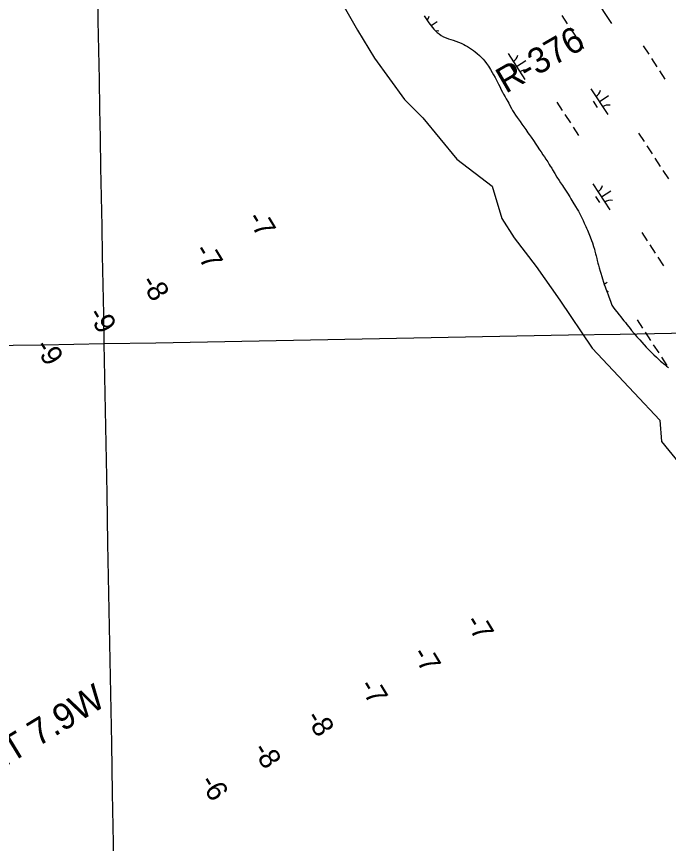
# Model space of a CAD drawing. Extents: x 3953924 to 3974542, y 193747 to 216192.
# Drawn here: x 3962352 to 3963404, y 205562 to 206897 of the extents above; entities that cross this region are included whole.
import ezdxf

# ---------------------------------------------------------------- set-up
doc = ezdxf.new("R2010")
doc.units = 0
for name, color, linetype in [('V-GRID-MAJR', 7, 'Continuous'), ('V-RIVR-EDGE', 7, 'Continuous'), ('V-RIVR-RANG', 7, 'Continuous'), ('V-RIVR-RANG-IDEN', 7, 'Continuous'), ('V-RRAP-SILL-IDEN', 7, 'Continuous'), ('V-WETL-SWMP', 7, 'Continuous')]:
    doc.layers.add(name, color=color, linetype=linetype)

msp = doc.modelspace()

# ---------------------------------------------------------------- linework, layer by layer
at = {"layer": 'V-GRID-MAJR'}
for points in [[(3962589.8, 201207.1), (3962493.7, 206368.6), (3962380.9, 212428.6), (3962369.3, 213053.2)], [(3959356.8, 206310.4), (3962493.7, 206368.6), (3967818.6, 206468.2), (3970066, 206510.4)]]:
    msp.add_spline(points, degree=3, dxfattribs=at)
at = {"layer": 'V-RIVR-EDGE'}
msp.add_lwpolyline([(3962880.7, 206912.3), (3962902.1, 206874.3), (3962929.4, 206829.2), (3962978.1, 206762.8), (3963007.8, 206733.1), (3963062.4, 206666.6), (3963119.4, 206622.7), (3963134.8, 206570.4), (3963155, 206539.6), (3963190.6, 206493.3), (3963228.6, 206438.6), (3963280.8, 206361.5), (3963348.5, 206289.1), (3963390.1, 206245.1), (3963392.4, 206210.7), (3963466, 206120.5), (3963492.2, 206108.6), (3963506.4, 206087.2), (3963530.1, 206054), (3963552.7, 206032.6), (3963582.4, 206007.7), (3963606.1, 205985.1), (3963619, 205957.3)], dxfattribs=at)
at = {"layer": 'V-WETL-SWMP'}
for p, q in [((3963284.5, 206927.4), (3963311.8, 206885.5)), ((3963231.7, 206898.4), (3963240.5, 206885)), ((3963009.8, 206897.7), (3963012, 206894.3)), ((3963012, 206894.3), (3963014.1, 206891.1)), ((3963014.1, 206891.1), (3963017.4, 206886.6)), ((3963017.4, 206886.6), (3963019.4, 206883.8)), ((3963020.8, 206882), (3963030.9, 206888.5)), ((3963019.4, 206883.8), (3963023.2, 206879)), ((3963023.2, 206879), (3963025.3, 206876.4)), ((3963025.3, 206876.4), (3963028.5, 206873.1)), ((3963028.5, 206873.1), (3963030.8, 206870.9)), ((3963244.8, 206878.3), (3963253.6, 206864.9)), ((3963030.8, 206870.9), (3963033.8, 206868.5)), ((3963033.8, 206868.5), (3963037.2, 206866.1)), ((3963037.2, 206866.1), (3963040.8, 206863.9)), ((3963040.8, 206863.9), (3963045.4, 206862.1)), ((3963045.4, 206862.1), (3963048.9, 206860.8)), ((3963048.9, 206860.8), (3963052.8, 206859.5)), ((3963052.8, 206859.5), (3963056.7, 206858.4)), ((3963056.7, 206858.4), (3963061, 206856.8)), ((3963257.9, 206858.2), (3963266.7, 206844.8)), ((3963061, 206856.8), (3963065.1, 206855.4)), ((3963065.1, 206855.4), (3963069.3, 206853.5)), ((3963069.3, 206853.5), (3963073.7, 206851.4)), ((3963073.7, 206851.4), (3963076.3, 206850)), ((3963076.3, 206850), (3963079.6, 206848.2)), ((3963079.6, 206848.2), (3963082.9, 206846.3)), ((3963082.9, 206846.3), (3963086.1, 206844.1)), ((3963363.1, 206849.1), (3963371.9, 206835.7)), ((3963086.1, 206844.1), (3963089.4, 206842)), ((3963089.4, 206842), (3963092.1, 206839.5)), ((3963092.1, 206839.5), (3963095.3, 206837)), ((3963095.3, 206837), (3963098.8, 206833.8)), ((3963098.8, 206833.8), (3963102.1, 206830.6)), ((3963145.1, 206836.7), (3963172.3, 206794.8)), ((3963102.1, 206830.6), (3963104.8, 206827.6)), ((3963104.8, 206827.6), (3963107.4, 206824.4)), ((3963107.4, 206824.4), (3963110.3, 206820.7)), ((3963110.3, 206820.7), (3963113.4, 206816.5)), ((3963158.7, 206815.7), (3963173.8, 206825.6)), ((3963376.2, 206829), (3963385, 206815.6)), ((3963113.4, 206816.5), (3963116.6, 206811.2)), ((3963116.6, 206811.2), (3963119.5, 206806.4)), ((3963119.5, 206806.4), (3963121.7, 206802.3)), ((3963149, 206816.6), (3963155.5, 206806.5)), ((3963389.3, 206808.9), (3963398.1, 206795.5)), ((3963121.7, 206802.3), (3963124, 206798)), ((3963124, 206798), (3963125.7, 206795.2)), ((3963125.7, 206795.2), (3963127.9, 206790.5)), ((3963127.9, 206790.5), (3963129.6, 206787.3)), ((3963129.6, 206787.3), (3963132.1, 206782.4)), ((3963132.1, 206782.4), (3963133.6, 206779.2)), ((3963133.6, 206779.2), (3963136, 206774.4)), ((3963278.5, 206780.1), (3963305.8, 206738.2)), ((3963136, 206774.4), (3963137.7, 206771.3)), ((3963137.7, 206771.3), (3963140.3, 206766.7)), ((3963140.3, 206766.7), (3963141.9, 206763.8)), ((3963292.1, 206759.1), (3963307.2, 206768.9)), ((3963141.9, 206763.8), (3963144.5, 206759.5)), ((3963144.5, 206759.5), (3963146.2, 206756.8)), ((3963146.2, 206756.8), (3963147.6, 206754.1)), ((3963147.6, 206754.1), (3963150.6, 206748)), ((3963223.7, 206758.4), (3963232.5, 206745)), ((3963282.4, 206759.9), (3963288.9, 206749.9)), ((3963150.6, 206748), (3963152.2, 206744.8)), ((3963152.2, 206744.8), (3963154.1, 206741.8)), ((3963154.1, 206741.8), (3963157.1, 206737.3)), ((3963236.8, 206738.3), (3963245.6, 206724.9)), ((3963157.1, 206737.3), (3963159.6, 206733.7)), ((3963159.6, 206733.7), (3963161.4, 206731.2)), ((3963161.4, 206731.2), (3963164.3, 206727)), ((3963164.3, 206727), (3963167.2, 206723.1)), ((3963167.2, 206723.1), (3963170.3, 206718.7)), ((3963170.3, 206718.7), (3963173.6, 206714)), ((3963173.6, 206714), (3963177, 206709)), ((3963249.9, 206718.2), (3963258.6, 206704.8)), ((3963177, 206709), (3963179.2, 206706)), ((3963179.2, 206706), (3963182.3, 206701.7)), ((3963182.3, 206701.7), (3963186, 206696.4)), ((3963355.6, 206708.2), (3963364.3, 206694.8)), ((3963186, 206696.4), (3963189.7, 206690.7)), ((3963189.7, 206690.7), (3963192.1, 206687.1)), ((3963192.1, 206687.1), (3963195.9, 206681.3)), ((3963368.7, 206688.1), (3963377.4, 206674.7)), ((3963195.9, 206681.3), (3963198.2, 206678)), ((3963198.2, 206678), (3963201.3, 206673.5)), ((3963201.3, 206673.5), (3963203.6, 206670)), ((3963203.6, 206670), (3963206, 206666.5)), ((3963206, 206666.5), (3963209, 206661.8)), ((3963209, 206661.8), (3963211.4, 206657.9)), ((3963381.7, 206668), (3963390.5, 206654.5)), ((3963211.4, 206657.9), (3963213.2, 206655.3)), ((3963213.2, 206655.3), (3963215.4, 206651.6)), ((3963215.4, 206651.6), (3963216.9, 206648.9)), ((3963216.9, 206648.9), (3963220.3, 206643.1)), ((3963394.8, 206647.8), (3963403.6, 206634.4)), ((3963220.3, 206643.1), (3963223.9, 206637.5)), ((3963223.9, 206637.5), (3963227.4, 206632.1)), ((3963227.4, 206632.1), (3963229.8, 206628.3)), ((3963229.8, 206628.3), (3963232.9, 206623.7)), ((3963232.9, 206623.7), (3963234.7, 206620.9)), ((3963234.7, 206620.9), (3963237.7, 206616.4)), ((3963282, 206626.4), (3963309.3, 206584.5)), ((3963237.7, 206616.4), (3963240.7, 206611.4)), ((3963240.7, 206611.4), (3963244.4, 206605.7)), ((3963244.4, 206605.7), (3963246.4, 206602.2)), ((3963285.9, 206606.2), (3963292.4, 206596.2)), ((3963295.6, 206605.4), (3963310.7, 206615.2)), ((3963246.4, 206602.2), (3963249.3, 206597)), ((3963249.3, 206597), (3963253.7, 206589.9)), ((3963253.7, 206589.9), (3963256.6, 206585.4)), ((3963256.6, 206585.4), (3963258.4, 206582.5)), ((3963258.4, 206582.5), (3963261, 206578)), ((3963261, 206578), (3963262.4, 206575.1)), ((3963262.4, 206575.1), (3963264.5, 206570.5)), ((3963264.5, 206570.5), (3963266, 206567.6)), ((3963266, 206567.6), (3963267.9, 206563.3)), ((3963267.9, 206563.3), (3963270.5, 206557.7)), ((3963270.5, 206557.7), (3963271.7, 206554.8)), ((3963271.7, 206554.8), (3963272.9, 206551.8)), ((3963272.9, 206551.8), (3963275.2, 206546.4)), ((3963275.2, 206546.4), (3963277.4, 206540.8)), ((3963277.4, 206540.8), (3963279.8, 206534.8)), ((3963360.6, 206548.1), (3963369.4, 206534.7)), ((3963279.8, 206534.8), (3963281.2, 206531.1)), ((3963281.2, 206531.1), (3963282.9, 206525.5)), ((3963282.9, 206525.5), (3963284.3, 206521.1)), ((3963373.7, 206528), (3963382.5, 206514.6)), ((3963284.3, 206521.1), (3963285.1, 206518.1)), ((3963285.1, 206518.1), (3963286.2, 206513.6)), ((3963286.2, 206513.6), (3963287.2, 206510.4)), ((3963287.2, 206510.4), (3963288.2, 206505.8)), ((3963288.2, 206505.8), (3963288.8, 206502.8)), ((3963288.8, 206502.8), (3963289.8, 206498.3)), ((3963289.8, 206498.3), (3963290.7, 206495.4)), ((3963386.8, 206507.9), (3963395.6, 206494.4)), ((3963290.7, 206495.4), (3963291.9, 206490.8)), ((3963291.9, 206490.8), (3963293.4, 206485.6)), ((3963293.4, 206485.6), (3963294.4, 206482.2)), ((3963294.4, 206482.2), (3963296.1, 206476.7)), ((3963296.1, 206476.7), (3963297.3, 206473)), ((3963297.3, 206473), (3963298.9, 206467.6)), ((3963298.9, 206467.6), (3963300.3, 206463.9)), ((3963299.9, 206464.8), (3963304.7, 206467.9)), ((3963300.3, 206463.9), (3963301.5, 206460.2)), ((3963301.5, 206460.2), (3963303, 206457.3)), ((3963303, 206457.3), (3963304.8, 206451.9)), ((3963304.8, 206451.9), (3963306.3, 206447.2)), ((3963306.3, 206447.2), (3963307.5, 206443.9)), ((3963307.5, 206443.9), (3963310, 206436.9)), ((3963310, 206436.9), (3963312.4, 206430.8)), ((3963312.4, 206430.8), (3963314.6, 206427.4)), ((3963314.6, 206427.4), (3963317.3, 206423.9)), ((3963317.3, 206423.9), (3963320.5, 206420)), ((3963320.5, 206420), (3963324.3, 206415.2)), ((3963324.3, 206415.2), (3963327, 206411.8)), ((3963327, 206411.8), (3963329.8, 206408)), ((3963329.8, 206408), (3963332, 206405.3)), ((3963332, 206405.3), (3963334.3, 206402.5)), ((3963353.1, 206407.1), (3963361.8, 206393.7)), ((3963334.3, 206402.5), (3963336.6, 206399.6)), ((3963336.6, 206399.6), (3963339.9, 206395.7)), ((3963339.9, 206395.7), (3963341.8, 206393.1)), ((3963341.8, 206393.1), (3963344.4, 206389.8)), ((3963344.4, 206389.8), (3963348.2, 206385.2)), ((3963348.2, 206385.2), (3963350.2, 206382.8)), ((3963350.2, 206382.8), (3963353, 206379.7)), ((3963353, 206379.7), (3963355.4, 206377.1)), ((3963366.2, 206387), (3963374.9, 206373.6)), ((3963355.4, 206377.1), (3963357.4, 206374.8)), ((3963357.4, 206374.8), (3963360.8, 206371.1)), ((3963360.8, 206371.1), (3963367.9, 206362.9)), ((3963379.2, 206366.9), (3963388, 206353.5)), ((3963367.9, 206362.9), (3963372.2, 206358.4)), ((3963372.2, 206358.4), (3963375.1, 206355.5)), ((3963375.1, 206355.5), (3963380, 206350.7)), ((3963380, 206350.7), (3963384.3, 206346.6)), ((3963384.3, 206346.6), (3963388, 206343)), ((3963388, 206343), (3963391.1, 206340.2)), ((3963391.1, 206340.2), (3963397.7, 206334.8)), ((3963392.3, 206346.8), (3963401.1, 206333.4)), ((3963397.7, 206334.8), (3963400.6, 206332.4)), ((3963400.6, 206332.4), (3963403.9, 206330.1))]:
    msp.add_line(p, q, dxfattribs=at)
for centre, start, end in [((3963000.9, 206902), 319.9514, 343.8338), ((3963031.1, 206855.7), 82.2901, 98.458), ((3963143.8, 206839), 302.2901, 343.8338), ((3963174, 206792.7), 82.2901, 123.8337), ((3963277.3, 206782.4), 302.2901, 343.8338), ((3963307.4, 206736.1), 82.2901, 123.8337), ((3963280.7, 206628.7), 302.2901, 343.8338), ((3963310.9, 206582.4), 82.2901, 123.8337), ((3963304.9, 206435), 82.2901, 91.1737)]:
    msp.add_arc(centre, 17.6, start, end, dxfattribs=at)

# ---------------------------------------------------------------- texts
at = {"layer": 'V-RIVR-RANG'}
for s, rotation, p in [('-7', 301.2005, (3962723.1, 206570.6)), ('-7', 301.2005, (3962637.6, 206518.7)), ('-8', 301.2005, (3962551.4, 206468.1)), ('-9', 301.2005, (3962466.1, 206415.9)), ('-9', 301.2005, (3962380.5, 206364.1)), ('-7', 301.2278, (3963074.7, 205919.7)), ('-7', 301.2278, (3962989.3, 205867.9)), ('-7', 301.2278, (3962903.8, 205816.1)), ('-8', 301.2278, (3962817.4, 205765.2)), ('-8', 301.2278, (3962732, 205713.5)), ('-6', 301.2278, (3962646.6, 205661.4))]:
    msp.add_text(s, height=33.5, rotation=rotation, dxfattribs=at).set_placement(p)
at = {"layer": 'V-RIVR-RANG-IDEN'}
msp.add_text('R-376  ', height=41.5, rotation=30.0536, dxfattribs=at).set_placement((3963141.3, 206771.6))
at = {"layer": 'V-RRAP-SILL-IDEN'}
msp.add_text('OUTLET 7.9W', height=42, rotation=31.2929, dxfattribs=at).set_placement((3962183.9, 205594.2))

doc.saveas('drawing.dxf')
